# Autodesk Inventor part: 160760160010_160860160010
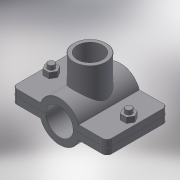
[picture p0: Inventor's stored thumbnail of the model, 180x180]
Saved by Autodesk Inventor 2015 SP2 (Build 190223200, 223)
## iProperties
Created: 2017-05
Part Number: 160760160010_160860160010
Material: Generic
Description: PLASSON SADDLE 160-1"
Document SubType Name: Modeling
Designer: KIM
Density: 1 g/cm^3
Appearance: Default
Author: KIM
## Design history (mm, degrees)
derived "16076.ipt"
feature "Solid1::16076.ipt"
feature "Solid2::16076.ipt"
tag "TaggingFeature1"
body "Solid1"
other parameters: "d0" = 176, "d1" = 223, "d4" = 145, "d5" = 0, "d6" = 11.15, "d7" = 223, "d8" = 0.1, "d10" = 0, "d11" = 1.6, "d14" = 39.3783, "d20" = 1.6, "d23" = 1.6, "d36" = 15, "d37" = 12, "d38" = 88, "d39" = 0, "d40" = 3, "d41" = 5, "d42" = 0, "d44" = 3, "d45" = 0, "d46" = 1.6, "d51" = 112, "d52" = 30.291, "d53" = 21, "d54" = 0, "d55" = 25, "d57" = 0, "d58" = 172.8, "d60" = 0, "d62" = 15, "d63" = 12, "d66" = 121, "B_" = 25, "G_" = 30.291, "A_" = 112, "L_" = 223, "L_1" = 145, "l_2" = 21
